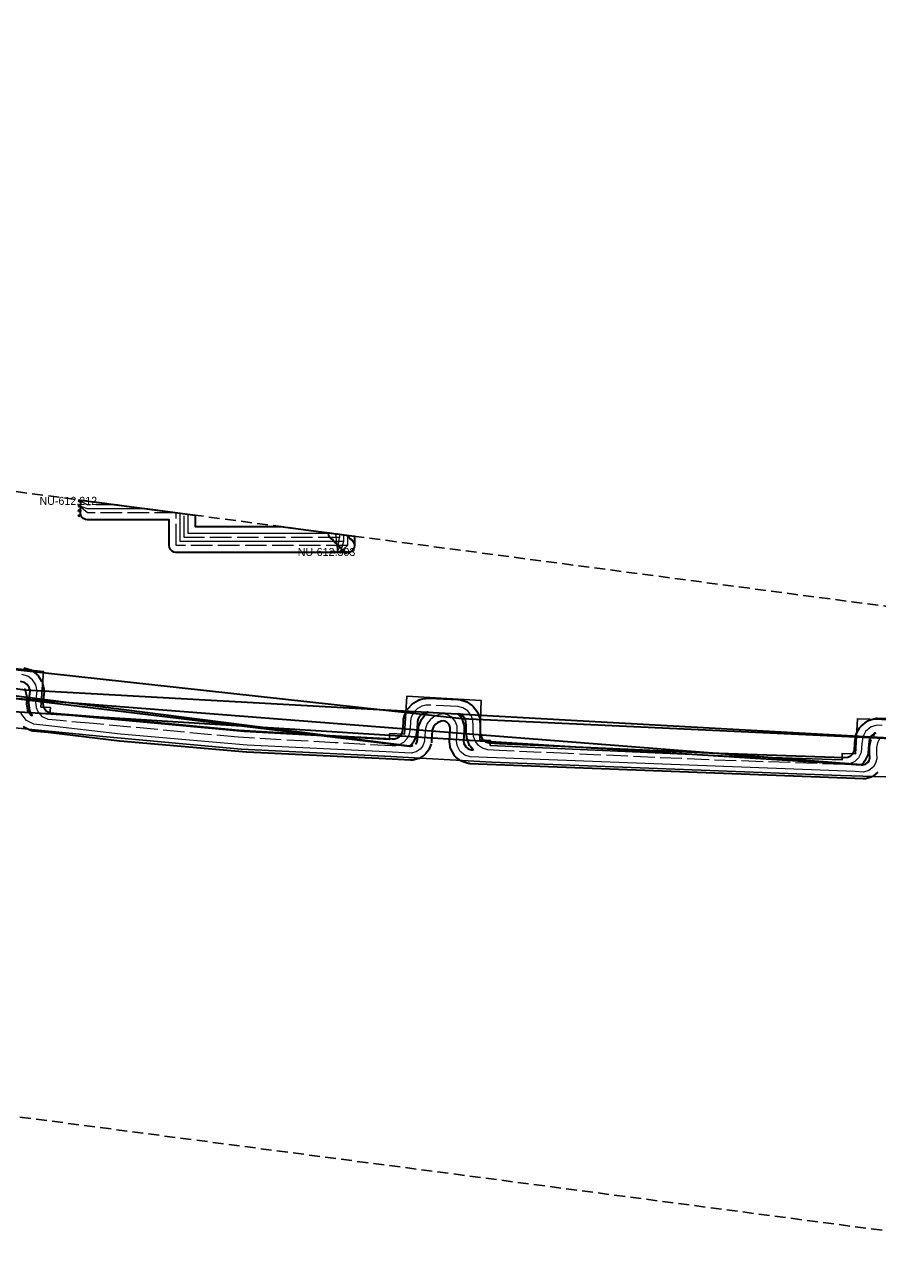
# Model space of a CAD drawing. Extents: x -451331 to -449998, y -1101254 to -1101132.
# Drawn here: x -450549.1 to -450463.8, y -1101253.5 to -1101132.1 of the extents above; entities that cross this region are included whole.
import ezdxf

# ---------------------------------------------------------------- set-up
doc = ezdxf.new("R2010")
doc.units = 0
doc.header["$LTSCALE"] = 0.36
doc.header["$PDMODE"] = 32
doc.header["$PDSIZE"] = 0.18
doc.linetypes.add('LONG_DASHED', pattern=[7.5, 6, -1.5])
doc.linetypes.add('MEDIUM_DASHED', pattern=[4.5, 3, -1.5])
for name, color, linetype, lineweight in [('2', 7, 'Continuous', 13), ('3', 7, 'Continuous', 25), ('62', 7, 'MEDIUM_DASHED', 25), ('8', 7, 'Continuous', 35)]:
    doc.layers.add(name, color=color, linetype=linetype, lineweight=lineweight)
doc.layers.add('4', color=7, linetype='Continuous')
doc.layers.add('7', color=7, linetype='Continuous')

msp = doc.modelspace()

# ---------------------------------------------------------------- linework, layer by layer
at = {"layer": '2', "linetype": 'LONG_DASHED'}
for p, q in [((-450542.759, -1101180.157), (-450543.576, -1101179.743)), ((-450542.759, -1101180.956), (-450543.59, -1101180.236)), ((-450517.755, -1101184.853), (-450517.56, -1101183.405)), ((-450517.56, -1101183.083), (-450517.56, -1101183.405)), ((-450516.76, -1101183.188), (-450516.76, -1101184.204)), ((-450516.76, -1101184.204), (-450517.469, -1101184.853))]:
    msp.add_line(p, q, dxfattribs=at)
at = {"layer": '2'}
for p, q in [((-450542.799, -1101179.756), (-450543.576, -1101179.743)), ((-450542.759, -1101180.557), (-450543.59, -1101180.236)), ((-450517.958, -1101183.03), (-450517.755, -1101184.853)), ((-450517.16, -1101183.135), (-450517.16, -1101183.804)), ((-450517.16, -1101183.804), (-450517.469, -1101184.853))]:
    msp.add_line(p, q, dxfattribs=at)
at = {"layer": '2', "linetype": 'LONG_DASHED'}
for points in [[(-450517.56, -1101183.405), (-450533.105, -1101183.405), (-450533.105, -1101181.034), (-450539.76, -1101180.157), (-450542.759, -1101180.157)], [(-450516.76, -1101184.204), (-450533.906, -1101184.204), (-450533.906, -1101180.956), (-450542.759, -1101180.956)], [(-450460.6, -1101202.279), (-450463.815, -1101202.179), (-450464.395, -1101202.349), (-450464.967, -1101202.815), (-450465.245, -1101203.334), (-450465.333, -1101204.021), (-450465.399, -1101204.893), (-450465.668, -1101205.441), (-450466.043, -1101205.804), (-450466.549, -1101206.044), (-450467.119, -1101206.1), (-450480.635, -1101205.635), (-450494.713, -1101205.015), (-450501.603, -1101204.694), (-450502.725, -1101204.637), (-450503.271, -1101204.469), (-450503.655, -1101204.203), (-450503.952, -1101203.837), (-450504.157, -1101203.313), (-450504.191, -1101202.925), (-450504.189, -1101202.278), (-450504.231, -1101201.64), (-450504.399, -1101201.193), (-450504.751, -1101200.742), (-450505.221, -1101200.434), (-450505.752, -1101200.293), (-450508.617, -1101200.171), (-450508.921, -1101200.184), (-450509.332, -1101200.286), (-450509.791, -1101200.541), (-450510.174, -1101200.942), (-450510.393, -1101201.364), (-450510.483, -1101201.733), (-450510.518, -1101202.566), (-450510.631, -1101203.181), (-450510.821, -1101203.535), (-450511.176, -1101203.905), (-450511.588, -1101204.135), (-450511.977, -1101204.232), (-450512.32, -1101204.239), (-450517.996, -1101203.932), (-450527.689, -1101203.379), (-450542.175, -1101202.009), (-450545.516, -1101201.718), (-450546.687, -1101201.606), (-450547.278, -1101201.331), (-450547.711, -1101200.851), (-450547.885, -1101200.427), (-450547.929, -1101199.879), (-450547.807, -1101198.735), (-450547.942, -1101198.142), (-450548.279, -1101197.629), (-450548.75, -1101197.278), (-450549.325, -1101197.105)]]:
    msp.add_lwpolyline(points, dxfattribs=at)
at = {"layer": '2'}
for points in [[(-450517.16, -1101183.804), (-450533.505, -1101183.804), (-450533.505, -1101180.981), (-450536.725, -1101180.557), (-450542.759, -1101180.557)], [(-450518.154, -1101183.004), (-450532.706, -1101183.004), (-450532.706, -1101181.086)], [(-450463.585, -1101203.55), (-450463.786, -1101203.928), (-450463.866, -1101204.418), (-450463.857, -1101204.934), (-450463.852, -1101205.536), (-450463.959, -1101205.964), (-450464.188, -1101206.339), (-450464.623, -1101206.69), (-450465.166, -1101206.853), (-450465.995, -1101206.807), (-450493.139, -1101205.783), (-450504.502, -1101205.325), (-450505.023, -1101205.174), (-450505.497, -1101204.81), (-450505.82, -1101204.217), (-450505.878, -1101203.745), (-450505.806, -1101202.727), (-450505.814, -1101202.268), (-450506.003, -1101201.757), (-450506.344, -1101201.363), (-450506.766, -1101201.122), (-450507.143, -1101201.035), (-450507.596, -1101201.088), (-450508.139, -1101201.323), (-450508.506, -1101201.624), (-450508.792, -1101202.013), (-450508.983, -1101202.507), (-450509.044, -1101203.181), (-450509.069, -1101203.786), (-450509.229, -1101204.227), (-450509.499, -1101204.576), (-450509.897, -1101204.848), (-450510.412, -1101204.982), (-450512.906, -1101204.824), (-450526.818, -1101204.182), (-450539.475, -1101203.059), (-450546.634, -1101202.221), (-450548.15, -1101202.064), (-450548.883, -1101201.702), (-450549.441, -1101200.956)]]:
    msp.add_lwpolyline(points, dxfattribs=at)
at = {"layer": '3'}
for points in [[(-450456.247, -1101207.547), (-450467.469, -1101207.201), (-450502.327, -1101205.863), (-450513.036, -1101205.268), (-450527.393, -1101204.583), (-450541.226, -1101203.307), (-450557.885, -1101201.66), (-450587.245, -1101198.634), (-450599.721, -1101197.12), (-450623.306, -1101194.193), (-450636.866, -1101192.511), (-450644.042, -1101191.642), (-450670.806, -1101187.894), (-450716.119, -1101180.809), (-450724.513, -1101179.55), (-450750.507, -1101175.197)], [(-450554.157, -1101196.058), (-450547.172, -1101196.789), (-450547.424, -1101200.367), (-450546.474, -1101200.403), (-450546.521, -1101200.99), (-450527.09, -1101202.8), (-450512.565, -1101203.608), (-450512.555, -1101203.01), (-450511.079, -1101203.063), (-450510.84, -1101199.285), (-450503.411, -1101199.687), (-450503.526, -1101203.648), (-450502.479, -1101203.687), (-450502.519, -1101204.197), (-450479.272, -1101205.232), (-450467.321, -1101205.642), (-450467.31, -1101204.989), (-450465.969, -1101205.033), (-450465.786, -1101201.536), (-450458.428, -1101201.743)]]:
    msp.add_lwpolyline(points, dxfattribs=at)
at = {"layer": '4'}
for p in [(-450543.576, -1101179.742), (-450543.591, -1101180.237), (-450517.754, -1101184.853), (-450517.47, -1101184.853)]:
    msp.add_point(p, dxfattribs=at)
at = {"layer": '62'}
msp.add_lwpolyline([(-450786.261, -1101210.25), (-451322.174, -1101190.711), (-451330.547, -1101132.096), (-450766.722, -1101150.239), (-450459.689, -1101190.711), (-449997.743, -1101194.898), (-449997.743, -1101249.327), (-450456.897, -1101253.514)], close=True, dxfattribs=at)
at = {"layer": '7'}
for p in [(-450543.576, -1101179.742), (-450543.605, -1101180.731), (-450543.591, -1101180.237), (-450543.62, -1101181.226), (-450517.754, -1101184.853), (-450517.47, -1101184.853), (-450518.372, -1101184.862), (-450518.087, -1101184.862), (-450516.908, -1101184.901), (-450516.624, -1101184.901)]:
    msp.add_point(p, dxfattribs=at)
at = {"layer": '8'}
for points in [[(-450549.096, -1101198.491), (-450549.05, -1101198.581), (-450549.017, -1101198.677), (-450719.127, -1101175.983)], [(-450726.33, -1101177.289), (-450505.347, -1101201.513), (-450505.157, -1101202.025), (-450505.126, -1101202.138), (-450505.114, -1101202.256), (-450505.106, -1101202.715), (-450505.106, -1101202.727), (-450505.108, -1101202.777), (-450505.175, -1101203.727), (-450505.142, -1101204), (-450504.954, -1101204.345), (-450504.701, -1101204.539), (-450504.389, -1101204.629), (-450504.204, -1101204.636), (-450504.495, -1101204.279), (-450504.557, -1101204.19), (-450504.604, -1101204.092), (-450504.809, -1101203.568), (-450504.839, -1101203.473), (-450504.854, -1101203.374), (-450504.889, -1101202.987), (-450504.89, -1101202.963), (-450504.891, -1101202.923), (-450504.89, -1101202.299), (-450504.923, -1101201.789), (-450505.017, -1101201.539), (-450505.232, -1101201.264), (-450505.51, -1101201.081), (-450505.708, -1101201.029), (-450505.474, -1101201.298), (-450505.423, -1101201.365), (-450505.381, -1101201.437), (-450505.347, -1101201.513), (-450460.204, -1101203.607)], [(-450724.607, -1101178.355), (-450510.557, -1101204.272), (-450510.479, -1101204.276), (-450510.191, -1101204.202)], [(-450509.985, -1101204.061), (-450509.85, -1101203.885), (-450509.764, -1101203.649), (-450509.744, -1101203.152), (-450509.743, -1101203.143), (-450509.741, -1101203.117), (-450509.68, -1101202.443), (-450509.664, -1101202.347), (-450509.636, -1101202.255), (-450509.445, -1101201.759), (-450509.406, -1101201.676), (-450509.356, -1101201.598), (-450509.07, -1101201.209), (-450509.014, -1101201.142), (-450508.95, -1101201.083), (-450508.697, -1101200.875), (-450508.82, -1101200.88), (-450509.073, -1101200.943), (-450509.358, -1101201.102), (-450509.599, -1101201.353), (-450509.733, -1101201.612), (-450509.786, -1101201.832), (-450509.818, -1101202.595), (-450509.822, -1101202.64), (-450509.829, -1101202.693), (-450509.943, -1101203.308), (-450509.971, -1101203.412), (-450510.014, -1101203.51), (-450510.203, -1101203.865), (-450510.254, -1101203.947), (-450510.316, -1101204.021), (-450510.557, -1101204.272), (-450593.919, -1101193.663)], [(-450464.203, -1101203.221), (-450464.145, -1101203.131), (-450464.075, -1101203.05), (-450463.98, -1101202.956), (-450464.062, -1101202.981), (-450464.416, -1101203.269), (-450464.567, -1101203.551), (-450464.636, -1101204.092), (-450464.701, -1101204.947), (-450464.714, -1101205.035), (-450464.737, -1101205.12), (-450464.771, -1101205.202), (-450465.04, -1101205.749), (-450465.102, -1101205.852), (-450465.181, -1101205.943), (-450465.384, -1101206.14), (-450598.72, -1101195.713)], [(-450549.123, -1101196.435), (-450548.548, -1101196.608), (-450548.436, -1101196.653), (-450548.332, -1101196.717), (-450547.861, -1101197.067), (-450547.799, -1101197.12), (-450547.743, -1101197.179), (-450547.694, -1101197.245), (-450547.357, -1101197.757), (-450547.316, -1101197.829), (-450547.283, -1101197.906), (-450547.26, -1101197.986), (-450547.124, -1101198.579), (-450547.108, -1101198.694), (-450547.111, -1101198.809), (-450547.226, -1101199.888), (-450547.196, -1101200.263), (-450547.11, -1101200.472), (-450546.854, -1101200.757), (-450546.501, -1101200.921), (-450545.452, -1101201.021), (-450542.112, -1101201.311), (-450527.637, -1101202.681), (-450517.957, -1101203.233), (-450512.308, -1101203.539), (-450512.071, -1101203.534), (-450511.848, -1101203.478), (-450511.608, -1101203.344), (-450511.393, -1101203.12), (-450511.3, -1101202.947), (-450511.215, -1101202.487), (-450511.182, -1101201.703), (-450511.163, -1101201.567), (-450511.073, -1101201.198), (-450511.048, -1101201.119), (-450511.015, -1101201.043)], [(-450460.204, -1101203.607), (-450549.017, -1101198.677), (-450548.847, -1101199.321), (-450548.827, -1101199.436), (-450548.826, -1101199.553), (-450548.867, -1101200.082), (-450548.776, -1101200.676), (-450548.422, -1101201.149), (-450548.317, -1101201.201), (-450548.358, -1101201.117), (-450548.533, -1101200.694), (-450548.566, -1101200.59), (-450548.583, -1101200.482), (-450548.626, -1101199.934), (-450548.629, -1101199.869), (-450548.625, -1101199.805), (-450548.515, -1101198.777), (-450548.597, -1101198.42), (-450548.796, -1101198.117), (-450549.07, -1101197.913), (-450549.465, -1101197.794)], [(-450510.796, -1101200.62), (-450510.744, -1101200.535), (-450510.68, -1101200.458), (-450510.296, -1101200.057), (-450510.219, -1101199.987), (-450510.131, -1101199.929), (-450509.673, -1101199.674), (-450509.589, -1101199.635), (-450509.502, -1101199.607), (-450509.088, -1101199.504), (-450509.013, -1101199.49), (-450508.95, -1101199.484), (-450508.647, -1101199.471), (-450508.636, -1101199.471), (-450508.588, -1101199.471), (-450505.722, -1101199.594), (-450505.647, -1101199.601), (-450505.572, -1101199.616), (-450505.042, -1101199.757), (-450504.936, -1101199.795), (-450504.838, -1101199.848), (-450504.368, -1101200.156), (-450504.277, -1101200.227), (-450504.2, -1101200.311), (-450503.847, -1101200.762), (-450503.789, -1101200.85), (-450503.744, -1101200.946), (-450503.576, -1101201.393), (-450503.547, -1101201.492), (-450503.532, -1101201.594), (-450503.491, -1101202.232), (-450503.49, -1101202.279), (-450503.491, -1101202.895), (-450503.469, -1101203.151), (-450503.34, -1101203.48), (-450503.174, -1101203.684), (-450502.962, -1101203.832), (-450502.603, -1101203.942), (-450501.569, -1101203.995), (-450494.681, -1101204.315), (-450480.608, -1101204.936), (-450467.142, -1101205.398), (-450466.738, -1101205.359), (-450466.447, -1101205.221), (-450466.243, -1101205.023), (-450466.087, -1101204.706), (-450466.031, -1101203.968), (-450466.027, -1101203.933), (-450465.94, -1101203.246), (-450465.924, -1101203.162), (-450465.898, -1101203.08), (-450465.862, -1101203.002), (-450465.583, -1101202.483), (-450465.535, -1101202.406), (-450465.476, -1101202.335), (-450465.409, -1101202.272), (-450464.838, -1101201.806), (-450464.762, -1101201.753), (-450464.68, -1101201.709), (-450464.593, -1101201.677), (-450464.013, -1101201.507), (-450463.904, -1101201.484), (-450463.793, -1101201.479), (-450460.579, -1101201.58)], [(-450553.859, -1101200.567), (-450465.384, -1101206.14), (-450465.25, -1101206.148), (-450464.956, -1101206.059), (-450464.722, -1101205.871), (-450464.612, -1101205.691), (-450464.553, -1101205.452), (-450464.556, -1101204.943), (-450464.566, -1101204.432), (-450464.565, -1101204.381), (-450464.557, -1101204.306), (-450464.477, -1101203.815), (-450464.45, -1101203.704), (-450464.404, -1101203.599)], [(-450463.748, -1101206.884), (-450464.183, -1101207.235), (-450464.256, -1101207.287), (-450464.336, -1101207.329), (-450464.421, -1101207.36), (-450464.965, -1101207.524), (-450465.084, -1101207.549), (-450465.206, -1101207.552), (-450466.028, -1101207.506), (-450493.166, -1101206.482), (-450504.53, -1101206.024), (-450504.614, -1101206.016), (-450504.696, -1101205.997), (-450505.217, -1101205.847), (-450505.299, -1101205.817), (-450505.377, -1101205.778), (-450505.449, -1101205.73), (-450505.924, -1101205.365), (-450505.996, -1101205.301), (-450506.06, -1101205.227), (-450506.112, -1101205.145), (-450506.435, -1101204.552), (-450506.472, -1101204.472), (-450506.499, -1101204.389), (-450506.515, -1101204.302), (-450506.573, -1101203.83), (-450506.578, -1101203.763), (-450506.576, -1101203.696), (-450506.506, -1101202.709), (-450506.512, -1101202.4), (-450506.616, -1101202.119), (-450506.795, -1101201.912), (-450507.023, -1101201.781), (-450507.182, -1101201.745), (-450507.413, -1101201.772), (-450507.771, -1101201.926), (-450507.994, -1101202.109), (-450508.173, -1101202.352), (-450508.295, -1101202.668), (-450508.346, -1101203.227), (-450508.37, -1101203.814), (-450508.382, -1101203.921)], [(-450508.411, -1101204.024), (-450508.571, -1101204.465), (-450508.615, -1101204.564), (-450508.675, -1101204.655), (-450508.945, -1101205.004), (-450509.019, -1101205.085), (-450509.104, -1101205.154), (-450509.502, -1101205.426), (-450509.607, -1101205.486), (-450509.721, -1101205.526), (-450510.236, -1101205.66), (-450510.345, -1101205.679), (-450510.456, -1101205.681), (-450512.944, -1101205.523), (-450526.85, -1101204.881), (-450526.88, -1101204.879), (-450539.537, -1101203.756), (-450539.556, -1101203.754), (-450546.711, -1101202.917), (-450548.222, -1101202.76), (-450548.304, -1101202.747), (-450548.383, -1101202.724), (-450548.459, -1101202.693), (-450549.193, -1101202.329)]]:
    msp.add_lwpolyline(points, dxfattribs=at)
for points in [[(-450516.877, -1101183.173), (-450516.749, -1101183.238), (-450516.594, -1101183.393), (-450516.511, -1101183.555), (-450516.349, -1101183.638), (-450516.194, -1101183.793), (-450516.095, -1101183.988), (-450516.06, -1101184.204), (-450516.095, -1101184.421), (-450516.194, -1101184.616), (-450516.349, -1101184.771), (-450516.544, -1101184.87), (-450516.76, -1101184.905), (-450533.906, -1101184.905), (-450534.122, -1101184.87), (-450534.317, -1101184.771), (-450534.472, -1101184.616), (-450534.571, -1101184.421), (-450534.605, -1101184.204), (-450534.605, -1101181.657), (-450542.759, -1101181.657), (-450542.976, -1101181.622), (-450543.171, -1101181.523), (-450543.326, -1101181.368), (-450543.425, -1101181.173), (-450543.46, -1101180.956), (-450543.428, -1101180.756), (-450543.46, -1101180.557), (-450543.428, -1101180.357), (-450543.46, -1101180.157), (-450543.428, -1101179.956), (-450543.46, -1101179.756), (-450543.446, -1101179.671), (-450532.005, -1101181.179), (-450532.005, -1101182.304), (-450523.465, -1101182.304)], [(-450517.81, -1101184.054), (-450517.972, -1101183.971), (-450518.127, -1101183.816), (-450518.21, -1101183.654), (-450518.372, -1101183.571), (-450518.527, -1101183.416), (-450518.626, -1101183.221), (-450518.66, -1101183.004), (-450518.66, -1101182.938), (-450516.06, -1101183.28), (-450516.06, -1101184.204), (-450516.095, -1101184.421), (-450516.194, -1101184.616), (-450516.349, -1101184.771), (-450516.544, -1101184.87), (-450516.76, -1101184.905), (-450516.977, -1101184.87), (-450517.172, -1101184.771), (-450517.327, -1101184.616), (-450517.41, -1101184.454), (-450517.572, -1101184.371), (-450517.727, -1101184.216)]]:
    msp.add_lwpolyline(points, close=True, dxfattribs=at)

# ---------------------------------------------------------------- texts
at = {"layer": '4'}
for s, p in [('NU-612.212', (-450547.576, -1101180.142)), ('NU-612.303', (-450521.754, -1101185.253))]:
    msp.add_text(s, height=0.8, dxfattribs=at).set_placement(p)

doc.saveas('drawing.dxf')
